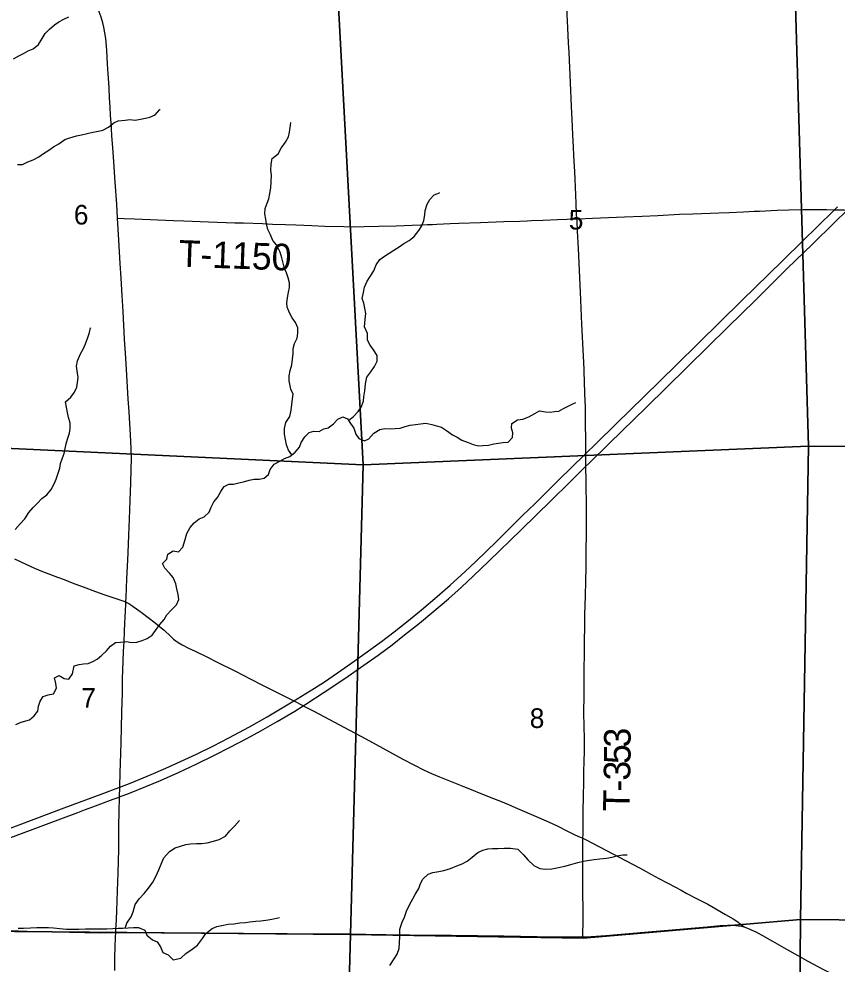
# Model space of a CAD drawing. Extents: x 0 to 34, y 0 to 22.
# Drawn here: x 11.919 to 13.666, y 11.182 to 13.199 of the extents above; entities that cross this region are included whole.
import ezdxf

# ---------------------------------------------------------------- set-up
doc = ezdxf.new("R2010")
doc.units = 0
for name, color, linetype in [('GM_X_County_Road', 7, 'Continuous'), ('GM_X_Interstate_Location', 7, 'Continuous'), ('GM_X_Interstate_Route', 7, 'Continuous'), ('GM_X_Minor_River', 7, 'Continuous'), ('GM_X_Section', 7, 'Continuous'), ('GM_X_Section_Text', 7, 'Continuous'), ('GM_X_State_Location', 7, 'Continuous'), ('GM_X_State_Route', 7, 'Continuous'), ('GM_X_Township_Road', 7, 'Continuous'), ('GM_X_Township_Road_Text', 7, 'Continuous')]:
    doc.layers.add(name, color=color, linetype=linetype)

msp = doc.modelspace()

# ---------------------------------------------------------------- linework, layer by layer
at = {"layer": 'GM_X_County_Road'}
for points in [[(13.1228, 11.2399), (13.1404, 11.2408), (13.1714, 11.2429), (13.2704, 11.2513), (13.3137, 11.2552), (13.354, 11.2584), (13.388, 11.2616), (13.4158, 11.2643), (13.4313, 11.2651), (13.4424, 11.2652), (13.4496, 11.2644), (13.4553, 11.2636), (13.4616, 11.2624), (13.4671, 11.2609)], [(13.4671, 11.2609), (13.4723, 11.2592), (13.478, 11.2569), (13.4823, 11.2551), (13.4923, 11.2503), (13.506, 11.243), (13.5275, 11.2307), (13.5572, 11.2137), (13.5814, 11.1998), (13.6032, 11.1878), (13.6363, 11.1705), (13.6668, 11.1552), (13.6919, 11.1429), (13.762, 11.1094), (13.8094, 11.0862), (13.843, 11.07), (13.8851, 11.05), (13.9075, 11.0392), (13.9465, 11.0201), (13.9745, 11.0065), (14.0109, 10.989), (14.0473, 10.9715), (14.078, 10.9566), (14.0833, 10.954)], [(11.8989, 11.2535), (11.9362, 11.2521), (11.9704, 11.2512), (11.9983, 11.2507), (12.0266, 11.25), (12.0426, 11.2496), (12.059, 11.2493), (12.074, 11.249), (12.0918, 11.2485), (12.1162, 11.2489), (12.1255, 11.2492)], [(12.1255, 11.2492), (12.1348, 11.2494), (12.1472, 11.2494), (12.172, 11.2492), (12.1937, 11.249), (12.2228, 11.2488), (12.259, 11.2486), (12.2846, 11.2484), (12.3146, 11.2482), (12.3395, 11.2478), (12.355, 11.2478), (12.3736, 11.2478), (12.3984, 11.2476), (12.4388, 11.2473), (12.4543, 11.247), (12.476, 11.2468), (12.4915, 11.2467), (12.5101, 11.2465), (12.5536, 11.2464), (12.6064, 11.246), (12.628, 11.246), (12.659, 11.2455), (12.6745, 11.2452), (12.7025, 11.2448), (12.7242, 11.2445), (12.7522, 11.2442), (12.777, 11.2438), (12.8111, 11.2434), (12.8422, 11.2432), (12.8763, 11.243), (12.898, 11.2426), (12.954, 11.2418), (13.0254, 11.2409), (13.0813, 11.2399), (13.1031, 11.2396), (13.1217, 11.2399), (13.1228, 11.2399)]]:
    msp.add_lwpolyline(points, dxfattribs=at)
at = {"layer": 'GM_X_Interstate_Route'}
for points in [[(11.8349, 11.448), (11.9194, 11.4792), (12.0154, 11.5153), (12.0941, 11.5443), (12.132, 11.5584), (12.1339, 11.5592), (12.1581, 11.5686), (12.2012, 11.5864), (12.2326, 11.5999), (12.2638, 11.614), (12.2975, 11.6299), (12.3337, 11.6478), (12.3669, 11.6649), (12.4107, 11.6885), (12.4487, 11.7097), (12.481, 11.7284), (12.5057, 11.7434), (12.5129, 11.7477), (12.5498, 11.7708), (12.5707, 11.7843), (12.5991, 11.8034), (12.6347, 11.8284), (12.6575, 11.8446), (12.6927, 11.8703), (12.7199, 11.891), (12.7468, 11.9122), (12.778, 11.9379), (12.8113, 11.966), (12.8393, 11.9905), (12.8716, 12.0197), (12.8943, 12.041), (12.9389, 12.0844), (12.9807, 12.1261), (12.994, 12.1391), (13.0208, 12.1651), (13.0694, 12.2131), (13.1005, 12.2436), (13.125, 12.2674), (13.1289, 12.2713), (13.1494, 12.2914), (13.1938, 12.3348), (13.2537, 12.3936), (13.3224, 12.4611), (13.4622, 12.5982), (13.5487, 12.6831), (13.5932, 12.7265), (13.6221, 12.7547), (13.6597, 12.7919), (13.6663, 12.7984)], [(12.1304, 11.5375), (12.1333, 11.5386), (12.1547, 11.5469), (12.1893, 11.5607), (12.2208, 11.5739), (12.2605, 11.5915), (12.2971, 11.6086), (12.3362, 11.6276), (12.3694, 11.6444), (12.4052, 11.6631), (12.4351, 11.6795), (12.4701, 11.6996), (12.5075, 11.7218), (12.5257, 11.7332), (12.5312, 11.7366), (12.5702, 11.762), (12.6142, 11.7913), (12.6551, 11.8195), (12.6854, 11.8411), (12.7152, 11.8635), (12.7422, 11.8844), (12.7737, 11.9097), (12.8, 11.9315), (12.8355, 11.9617), (12.8634, 11.9864), (12.8885, 12.0096), (12.9222, 12.0417), (12.9913, 12.1089), (13.0555, 12.1721), (13.0931, 12.2092), (13.1265, 12.2417), (13.1292, 12.2443), (13.1355, 12.2504), (13.1799, 12.2938), (13.2575, 12.37), (13.4329, 12.5419), (13.4906, 12.5984), (13.5591, 12.6662), (13.6127, 12.7181), (13.6592, 12.7639), (13.687, 12.7913)], [(11.8957, 11.4501), (11.9773, 11.4804), (12.0443, 11.5053), (12.0587, 11.5109), (12.0763, 11.5174), (12.0938, 11.5237), (12.12, 11.5335), (12.1304, 11.5375)]]:
    msp.add_lwpolyline(points, dxfattribs=at)
at = {"layer": 'GM_X_Minor_River'}
for points in [[(11.9069, 13.1138), (11.9186, 13.1201), (11.9285, 13.1253), (11.9381, 13.1309), (11.9491, 13.1354), (11.9601, 13.1448), (11.9682, 13.1576), (11.9743, 13.1682), (11.9839, 13.1775), (11.9946, 13.1869), (12.0041, 13.1929), (12.0147, 13.1989), (12.0254, 13.2033)], [(11.9159, 12.8883), (11.9265, 12.8882), (11.9379, 12.8942), (11.9493, 12.8982), (11.9611, 12.9049), (11.9714, 12.912), (11.9828, 12.9191), (11.9927, 12.9259), (12.0038, 12.9326), (12.0163, 12.942), (12.0274, 12.9457), (12.0414, 12.9497), (12.052, 12.9519), (12.0645, 12.9544), (12.0763, 12.9573), (12.0884, 12.9599), (12.0979, 12.9617), (12.1101, 12.9684), (12.1212, 12.9774), (12.1307, 12.9815), (12.1451, 12.9828), (12.1553, 12.9843), (12.167, 12.983), (12.178, 12.9852), (12.1886, 12.9873), (12.1981, 12.9895), (12.2095, 12.9943), (12.2198, 13.0056), (12.2199, 13.006)], [(12.5015, 12.2688), (12.4943, 12.279), (12.4902, 12.29), (12.4877, 12.3014), (12.4859, 12.3132), (12.4856, 12.3246), (12.4883, 12.3378), (12.4972, 12.3503), (12.4999, 12.3639), (12.5015, 12.3764), (12.5024, 12.3882), (12.504, 12.3984), (12.4995, 12.4091), (12.4959, 12.4266), (12.4956, 12.4372), (12.498, 12.4489), (12.5015, 12.461), (12.504, 12.4853), (12.5041, 12.4959), (12.5072, 12.5061), (12.513, 12.5178), (12.5142, 12.5284), (12.5139, 12.5398), (12.5091, 12.5513), (12.5023, 12.5612), (12.496, 12.5719), (12.4916, 12.5837), (12.4909, 12.5932), (12.4921, 12.6038), (12.4945, 12.6159), (12.4965, 12.6261), (12.4962, 12.636), (12.4936, 12.6467), (12.4899, 12.6573), (12.4858, 12.6668), (12.4825, 12.6779), (12.4796, 12.6893), (12.4763, 12.7015), (12.4685, 12.7167), (12.4606, 12.7263), (12.4554, 12.7381), (12.4502, 12.7495), (12.4473, 12.7621), (12.4458, 12.7716), (12.4433, 12.7834), (12.4441, 12.7947), (12.4484, 12.8057), (12.4519, 12.8155), (12.4542, 12.8265), (12.4566, 12.839), (12.4575, 12.8519), (12.458, 12.8659), (12.4566, 12.8766), (12.457, 12.8891), (12.4594, 12.9012), (12.472, 12.911), (12.4782, 12.9234), (12.4877, 12.9359), (12.4943, 12.9472), (12.4962, 12.9574), (12.4994, 12.9771), (12.4975, 12.9767)], [(12.6224, 12.3418), (12.6327, 12.3508), (12.6427, 12.361), (12.6496, 12.3708), (12.6542, 12.3833), (12.655, 12.3927), (12.657, 12.4053), (12.6583, 12.4204), (12.6611, 12.4344), (12.6703, 12.4457), (12.6779, 12.457), (12.6837, 12.4687), (12.6834, 12.4805), (12.6756, 12.4931), (12.6688, 12.5027), (12.6629, 12.5137), (12.663, 12.5278), (12.6563, 12.5422), (12.6576, 12.5578), (12.6592, 12.5703), (12.6574, 12.5817), (12.6548, 12.5927), (12.6515, 12.6026), (12.6543, 12.6151), (12.6563, 12.6265), (12.6621, 12.6393), (12.6686, 12.6495), (12.6763, 12.6612), (12.6817, 12.6744), (12.6893, 12.6854), (12.6992, 12.6928), (12.7091, 12.6992), (12.719, 12.7059), (12.7305, 12.7126), (12.7404, 12.7198), (12.7518, 12.7265), (12.7625, 12.7351), (12.7724, 12.7475), (12.7789, 12.7577), (12.7828, 12.7687), (12.7852, 12.7808), (12.786, 12.7903), (12.7899, 12.8039), (12.7961, 12.8137), (12.8049, 12.8235), (12.8163, 12.8283), (12.8159, 12.8287)], [(12.0059, 12.2401), (12.0075, 12.2499), (12.011, 12.2605), (12.0152, 12.2719), (12.0176, 12.2825), (12.0196, 12.2923), (12.0223, 12.3025), (12.0269, 12.315), (12.0282, 12.3249), (12.0279, 12.337), (12.0242, 12.3484), (12.0224, 12.3591), (12.0202, 12.3705), (12.0184, 12.3819), (12.0291, 12.392), (12.0375, 12.4026), (12.0422, 12.4131), (12.0438, 12.423), (12.045, 12.4336), (12.0436, 12.4431), (12.0418, 12.4583), (12.0434, 12.4697), (12.05, 12.484), (12.0565, 12.4957), (12.0607, 12.5059), (12.0658, 12.5192), (12.0693, 12.5297), (12.0716, 12.5396), (12.0716, 12.5392)], [(12.2533, 11.9933), (12.2477, 12.0066), (12.2402, 12.0162), (12.2301, 12.0265), (12.2249, 12.0365), (12.2344, 12.0462), (12.2368, 12.0565), (12.2482, 12.0639), (12.2596, 12.0619), (12.2687, 12.0717), (12.2734, 12.088), (12.2773, 12.1005), (12.2839, 12.1133), (12.293, 12.1238), (12.3033, 12.1321), (12.3143, 12.1361), (12.3247, 12.1467), (12.3289, 12.1569), (12.3347, 12.1682), (12.3423, 12.178), (12.35, 12.1908), (12.3569, 12.201), (12.3668, 12.2058), (12.3767, 12.2061), (12.388, 12.2087), (12.3979, 12.2108), (12.41, 12.2145), (12.4211, 12.2171), (12.4317, 12.217), (12.4419, 12.2188), (12.4518, 12.2266), (12.4553, 12.2376), (12.4637, 12.2485), (12.4759, 12.2552), (12.4858, 12.2608), (12.4972, 12.2653), (12.5082, 12.2743), (12.5174, 12.2852), (12.5209, 12.2954), (12.529, 12.3071), (12.5385, 12.3165), (12.5484, 12.319), (12.5594, 12.3186), (12.5696, 12.3241), (12.5791, 12.3267), (12.5902, 12.3346), (12.5997, 12.3447), (12.61, 12.3496), (12.6198, 12.3453), (12.6269, 12.3357), (12.634, 12.3254), (12.6381, 12.3132), (12.6441, 12.3037), (12.6561, 12.2983), (12.666, 12.3031), (12.6767, 12.3148), (12.6889, 12.323), (12.6999, 12.3251), (12.7113, 12.3243), (12.7219, 12.3253), (12.7325, 12.3256), (12.7435, 12.3289), (12.7541, 12.3318), (12.7651, 12.3336), (12.7761, 12.3346), (12.7875, 12.3361), (12.7999, 12.3337), (12.8101, 12.3309), (12.8211, 12.3278), (12.8313, 12.3208), (12.8441, 12.3116), (12.8542, 12.3062), (12.8644, 12.3), (12.8776, 12.295), (12.8886, 12.2911), (12.8995, 12.2883), (12.9094, 12.289), (12.9215, 12.2896), (12.9329, 12.2921), (12.9424, 12.2939), (12.9518, 12.295), (12.9632, 12.2956), (12.9724, 12.3054), (12.9732, 12.3156), (12.9703, 12.3255), (12.9711, 12.3358), (12.9829, 12.3436), (12.9947, 12.3447), (13.0076, 12.3495), (13.0202, 12.3569), (13.0301, 12.3625), (13.0429, 12.3605), (13.0527, 12.3596), (13.0622, 12.3611), (13.0717, 12.3621), (13.0816, 12.3673), (13.0915, 12.3729), (13.1014, 12.3778), (13.1075, 12.3804)], [(11.9105, 12.1097), (11.9212, 12.1218), (11.9315, 12.1319), (11.9396, 12.1455), (11.9487, 12.1564), (11.9583, 12.1654), (11.9678, 12.1752), (11.9781, 12.1831), (11.9873, 12.1947), (11.9935, 12.2068), (11.9981, 12.217), (12.0024, 12.2299), (12.0059, 12.2401)], [(11.9122, 11.6931), (11.9233, 11.6983), (11.9411, 11.703), (11.951, 11.7113), (11.9591, 11.7214), (11.9603, 11.7324), (11.9638, 11.7427), (11.9703, 11.7528), (11.9813, 11.7565), (11.9927, 11.7583), (11.9989, 11.7708), (11.9974, 11.781), (11.9949, 11.7924), (12.0048, 11.7977), (12.0153, 11.7911), (12.0255, 11.7902), (12.0332, 11.8012), (12.0364, 11.8186), (12.047, 11.8215), (12.0565, 11.8226), (12.0667, 11.8236), (12.0762, 11.8273), (12.0857, 11.8329), (12.0953, 11.8412), (12.1059, 11.8502), (12.1143, 11.86), (12.125, 11.8682), (12.1352, 11.8692), (12.1478, 11.8703), (12.1595, 11.8682), (12.1705, 11.8689), (12.1815, 11.8726), (12.1921, 11.8767), (12.2028, 11.8838), (12.2104, 11.8935), (12.2192, 11.9064), (12.2284, 11.9173), (12.2346, 11.9271), (12.2437, 11.9372), (12.2548, 11.9485), (12.2598, 11.9602), (12.2584, 11.9705), (12.2559, 11.9827), (12.2533, 11.9933)], [(12.1456, 11.2586), (12.1491, 11.2691), (12.1585, 11.2828), (12.1623, 11.2931), (12.1671, 11.309), (12.1755, 11.3212), (12.1857, 11.3326), (12.1951, 11.3436), (12.2042, 11.3566), (12.2117, 11.3702), (12.2174, 11.3828), (12.2238, 11.3984), (12.2283, 11.4086), (12.24, 11.4223), (12.2525, 11.4296), (12.2639, 11.4334), (12.2753, 11.4368), (12.2847, 11.4384), (12.298, 11.4388), (12.3086, 11.4388), (12.3204, 11.4408), (12.3337, 11.4438), (12.3462, 11.4477), (12.3594, 11.4549), (12.3692, 11.4663), (12.3787, 11.4759), (12.3897, 11.488)], [(12.7104, 11.1786), (12.7198, 11.1927), (12.7262, 11.2026), (12.7304, 11.2147), (12.7315, 11.2273), (12.7322, 11.2409), (12.7318, 11.2565), (12.737, 11.2709), (12.7415, 11.2819), (12.7464, 11.2945), (12.7525, 11.3081), (12.7593, 11.3207), (12.7645, 11.3302), (12.7725, 11.3431), (12.7759, 11.3534), (12.7811, 11.3632), (12.7925, 11.3735), (12.8023, 11.3774), (12.8152, 11.3797), (12.8255, 11.3816), (12.8403, 11.3858), (12.8539, 11.3912), (12.8653, 11.3958), (12.8755, 11.4015), (12.8861, 11.4099), (12.8982, 11.4201), (12.9092, 11.4247), (12.9198, 11.4274), (12.93, 11.4286), (12.9414, 11.4286), (12.9543, 11.429), (12.968, 11.4291), (12.9839, 11.4268), (12.9957, 11.4151), (13.0052, 11.4045), (13.0181, 11.3924), (13.0311, 11.386), (13.0425, 11.3845), (13.0565, 11.3853), (13.0709, 11.3877), (13.0845, 11.3907), (13.0971, 11.3942), (13.1118, 11.3984), (13.1243, 11.4011), (13.1372, 11.4038), (13.1467, 11.405), (13.1589, 11.4061), (13.1733, 11.4077), (13.185, 11.41), (13.1949, 11.4127), (13.2081, 11.415), (13.2176, 11.415)], [(11.9173, 11.2582), (11.9283, 11.2586), (11.9431, 11.2594), (11.9571, 11.2598), (11.9708, 11.2595), (11.9818, 11.2599), (11.9924, 11.2591), (12.0057, 11.2577), (12.0205, 11.2566), (12.0368, 11.2563), (12.0463, 11.2563), (12.0611, 11.2567), (12.0732, 11.2571), (12.1066, 11.2572), (12.1191, 11.2576), (12.1305, 11.2581), (12.1404, 11.2581), (12.1521, 11.2593), (12.1635, 11.2597), (12.1741, 11.2601), (12.1874, 11.2544), (12.1916, 11.2438), (12.2038, 11.2336), (12.214, 11.2295), (12.2209, 11.2185), (12.2262, 11.2067), (12.2373, 11.2018), (12.2479, 11.1905), (12.2642, 11.1947), (12.2752, 11.2046), (12.2888, 11.2138), (12.2998, 11.2221), (12.3107, 11.2362), (12.3179, 11.2472), (12.3312, 11.2579), (12.3414, 11.2617), (12.3516, 11.2644), (12.3657, 11.2667), (12.3774, 11.2679), (12.3903, 11.2695), (12.4021, 11.2706), (12.4119, 11.2718), (12.4244, 11.273), (12.4354, 11.2742), (12.451, 11.2761), (12.462, 11.278)], [(12.462, 11.278), (12.4749, 11.2811)]]:
    msp.add_lwpolyline(points, dxfattribs=at)
at = {"layer": 'GM_X_Section'}
for points in [[(12.4929, 13.3075), (12.5967, 13.3052), (12.6535, 12.2476), (11.5966, 12.2962), (11.6037, 13.3127)], [(13.5034, 13.3022), (13.5746, 13.3006), (13.6043, 12.2869), (12.6535, 12.2476), (12.5967, 13.3052)], [(14.5623, 13.2983), (14.5977, 12.2808), (13.6043, 12.2869), (13.5746, 13.3006), (14.5077, 13.2997)], [(11.5966, 12.2962), (12.6535, 12.2476), (12.6265, 11.2451), (11.591, 11.2544), (11.5914, 11.2691), (11.5959, 12.2894)], [(13.6043, 12.2869), (13.5876, 11.2769), (13.123, 11.237), (12.6265, 11.2451), (12.6535, 12.2476)], [(13.6043, 12.2869), (14.5977, 12.2808), (14.5738, 11.2682), (13.5876, 11.2769)], [(12.6265, 11.2451), (13.123, 11.237), (13.5876, 11.2769), (13.5789, 10.274), (13.086, 10.2295), (12.599, 10.2335)], [(13.5876, 11.2769), (14.5738, 11.2682), (14.5701, 10.2676), (13.5789, 10.274)], [(11.591, 11.2544), (12.6265, 11.2451), (12.599, 10.2335), (11.5847, 10.2523), (11.5843, 10.269)]]:
    msp.add_lwpolyline(points, close=True, dxfattribs=at)
at = {"layer": 'GM_X_State_Route'}
for points in [[(12.108, 13.1024), (12.1061, 13.1327), (12.104, 13.1574), (12.1023, 13.1697), (12.1, 13.1818), (12.0977, 13.1908), (12.0941, 13.2026), (12.0898, 13.2142), (12.0849, 13.2256), (12.0755, 13.2452), (12.0561, 13.2841), (12.0441, 13.3076)], [(12.1232, 11.1679), (12.1237, 11.1959), (12.1242, 11.2176), (12.125, 11.2393), (12.1255, 11.2492), (12.1258, 11.2548), (12.1267, 11.2765), (12.1273, 11.2965), (12.1282, 11.3151), (12.1292, 11.3393), (12.1297, 11.3561), (12.1304, 11.3773), (12.131, 11.399), (12.1317, 11.4283), (12.1321, 11.4593), (12.132, 11.4806), (12.1324, 11.5022), (12.1326, 11.5146), (12.133, 11.5302), (12.1333, 11.5386), (12.1339, 11.5592), (12.134, 11.5612), (12.1349, 11.5892), (12.1355, 11.6114), (12.136, 11.6308), (12.1367, 11.6552), (12.1376, 11.6861), (12.1386, 11.7198), (12.1397, 11.7597), (12.1395, 11.7905), (12.1412, 11.8282), (12.1421, 11.8493), (12.1433, 11.8704), (12.1441, 11.8919), (12.1448, 11.9096), (12.1455, 11.9221), (12.146, 11.9361), (12.1467, 11.9495), (12.1471, 11.9548), (12.1477, 11.9645), (12.1493, 12.0041), (12.151, 12.0443), (12.1516, 12.0598), (12.1533, 12.097), (12.1548, 12.1311), (12.1563, 12.1714), (12.1574, 12.2087), (12.1584, 12.2366), (12.1588, 12.2614), (12.1585, 12.28), (12.1577, 12.2986), (12.1539, 12.3606), (12.1519, 12.3885), (12.1499, 12.4258), (12.1484, 12.4506), (12.1469, 12.4754), (12.1443, 12.5157), (12.141, 12.5746), (12.1389, 12.6087), (12.1371, 12.6459), (12.1351, 12.6769), (12.1322, 12.7266), (12.1293, 12.7741), (12.1275, 12.8041), (12.1241, 12.8506), (12.1211, 12.894), (12.1188, 12.9249), (12.1172, 12.9498), (12.1162, 12.9652), (12.1154, 12.9776), (12.1144, 12.9931), (12.1133, 13.0117), (12.1123, 13.0303), (12.111, 13.052), (12.1087, 13.0924), (12.108, 13.1024)]]:
    msp.add_lwpolyline(points, dxfattribs=at)
at = {"layer": 'GM_X_Township_Road'}
for points in [[(13.1046, 12.8843), (13.1034, 12.9074), (13.1025, 12.926), (13.1012, 12.9508), (13.1003, 12.9694), (13.0984, 13.0128), (13.0962, 13.0625), (13.0931, 13.1276), (13.092, 13.1484), (13.0905, 13.1803), (13.0891, 13.2084), (13.0874, 13.2518), (13.0861, 13.2786), (13.0858, 13.2887), (13.0851, 13.2951), (13.084, 13.2984), (13.0824, 13.3009), (13.0802, 13.3029), (13.0779, 13.3042), (13.0751, 13.3054), (13.0722, 13.306), (13.0696, 13.3064)], [(13.1101, 12.7727), (13.1094, 12.7834), (13.1086, 12.8051), (13.1078, 12.8237), (13.1052, 12.8733), (13.1046, 12.8843)], [(13.4884, 12.7885), (13.5001, 12.7889), (13.5374, 12.7908), (13.5622, 12.7917), (13.5933, 12.7926), (13.6182, 12.7927), (13.6431, 12.7922), (13.6597, 12.7919), (13.6804, 12.7914), (13.687, 12.7913), (13.7053, 12.7911), (13.7923, 12.7901), (13.8202, 12.7897), (13.8513, 12.7892), (13.8642, 12.789)], [(12.1293, 12.7741), (12.1434, 12.7734), (12.1651, 12.7722), (12.2489, 12.7687), (12.2707, 12.768), (12.3235, 12.7663), (12.3793, 12.7643), (12.3983, 12.7636), (12.4384, 12.7622), (12.4601, 12.7614), (12.4881, 12.7606), (12.5099, 12.7596), (12.544, 12.7581), (12.5719, 12.757), (12.6123, 12.7558), (12.6341, 12.7557), (12.6558, 12.7558), (12.6869, 12.7565), (12.7241, 12.7578), (12.7583, 12.7592), (12.777, 12.7599), (12.7899, 12.7603)], [(12.7899, 12.7603), (12.8018, 12.7607), (12.8111, 12.7612), (12.839, 12.7624), (12.8576, 12.7631), (12.9042, 12.7646), (12.954, 12.7665), (12.9881, 12.7678), (13.0037, 12.7685), (13.013, 12.7689), (13.0378, 12.7697), (13.0688, 12.7712), (13.1101, 12.7727)], [(13.1101, 12.7727), (13.1123, 12.7728), (13.1433, 12.7736), (13.1775, 12.7752), (13.2118, 12.7767), (13.249, 12.778), (13.2827, 12.7795), (13.3292, 12.7821), (13.3572, 12.7833), (13.4131, 12.7853), (13.4349, 12.7863), (13.4659, 12.7875), (13.4884, 12.7885)], [(13.1257, 12.4445), (13.1254, 12.4514), (13.1243, 12.4793), (13.1208, 12.5476), (13.1175, 12.6158), (13.1134, 12.709), (13.1115, 12.7462), (13.1104, 12.7679), (13.1101, 12.7727)], [(13.1299, 12.0574), (13.13, 12.0634), (13.1306, 12.1007), (13.1306, 12.1286), (13.1306, 12.1659), (13.1298, 12.2), (13.1294, 12.2155), (13.1292, 12.2404), (13.1292, 12.2443), (13.1289, 12.2683), (13.1289, 12.2713), (13.1287, 12.2963), (13.1284, 12.3397), (13.128, 12.371), (13.1271, 12.3988), (13.1264, 12.4266), (13.1257, 12.4445)], [(11.9092, 12.0464), (11.9318, 12.036), (11.9516, 12.0271), (11.9687, 12.0198), (11.9803, 12.0154), (12.0007, 12.0079), (12.0153, 12.0025), (12.0326, 11.9956), (12.0617, 11.9846), (12.082, 11.9768), (12.0996, 11.9705), (12.1424, 11.9567), (12.1471, 11.9548)], [(13.1229, 11.4504), (13.1231, 11.4591), (13.1236, 11.5088), (13.1242, 11.5398), (13.1245, 11.5709), (13.1246, 11.5802), (13.1248, 11.5926), (13.1253, 11.6143), (13.1259, 11.636), (13.126, 11.6453), (13.1259, 11.6576), (13.1259, 11.6669), (13.1259, 11.6731), (13.1258, 11.6791), (13.1257, 11.6822), (13.1257, 11.6852), (13.1252, 11.6941), (13.1253, 11.7001), (13.1251, 11.7073), (13.1251, 11.7165), (13.1251, 11.7271), (13.1256, 11.7468), (13.1252, 11.7661), (13.1255, 11.7809), (13.1256, 11.7933), (13.1256, 11.8158), (13.1261, 11.8399), (13.1262, 11.8748), (13.1267, 11.8994), (13.1271, 11.9276), (13.1281, 11.9669), (13.1289, 11.9995), (13.1294, 12.0275), (13.1299, 12.0574)], [(12.1471, 11.9548), (12.1492, 11.9539), (12.1535, 11.9513), (12.1573, 11.9489), (12.1748, 11.9363), (12.1823, 11.9309), (12.1948, 11.9218), (12.2096, 11.9104), (12.2191, 11.9025), (12.2284, 11.8942), (12.2419, 11.8814), (12.2488, 11.8752), (12.2537, 11.8714), (12.2588, 11.8679), (12.2668, 11.8633), (12.2807, 11.8564), (12.2947, 11.8498), (12.3198, 11.8377), (12.342, 11.8265), (12.3809, 11.8071), (12.414, 11.79), (12.4388, 11.7772), (12.4971, 11.7478), (12.5057, 11.7434), (12.5248, 11.7337), (12.5257, 11.7332), (12.5496, 11.7208), (12.6018, 11.6932), (12.6594, 11.6625), (12.6812, 11.6505), (12.7385, 11.6192), (12.7632, 11.606), (12.7826, 11.5962), (12.7995, 11.5884), (12.8167, 11.5812), (12.8629, 11.5627), (12.9264, 11.5373), (12.9466, 11.5293), (12.9638, 11.5221), (12.9781, 11.5161), (13.0182, 11.499), (13.0494, 11.4851), (13.069, 11.4758), (13.0885, 11.4661), (13.1024, 11.4591), (13.1137, 11.454), (13.1193, 11.4518), (13.1229, 11.4504)], [(13.1228, 11.2399), (13.1228, 11.2449), (13.1231, 11.2728), (13.123, 11.2976), (13.1226, 11.3349), (13.1224, 11.3659), (13.1223, 11.3939), (13.1225, 11.4187), (13.1225, 11.4343), (13.1229, 11.4504)], [(13.1229, 11.4504), (13.1296, 11.4467), (13.2433, 11.3875)], [(13.2433, 11.3875), (13.2516, 11.3828), (13.2691, 11.3729), (13.2848, 11.3647), (13.3039, 11.3547)], [(13.3039, 11.3547), (13.3056, 11.3538), (13.3323, 11.3396), (13.3448, 11.3324), (13.3642, 11.3227), (13.3893, 11.3095), (13.4272, 11.2878), (13.4434, 11.2783), (13.4512, 11.2732), (13.4543, 11.271), (13.4559, 11.2697), (13.4597, 11.2668), (13.4632, 11.2639), (13.4671, 11.2609)]]:
    msp.add_lwpolyline(points, dxfattribs=at)

# ---------------------------------------------------------------- texts
at = {"layer": 'GM_X_Interstate_Location'}
for s in ['.', '-', ',']:
    msp.add_text(s, height=0.000189, dxfattribs=at).set_placement((13.0142, 12.1318))
msp.add_text('71', height=0.000189, rotation=0, dxfattribs=at).set_placement((12.9755, 12.0926))
at = {"layer": 'GM_X_Section_Text'}
for s, p in [('6', (12.0359, 12.7603)), ('5', (13.0926, 12.7496)), ('7', (12.0518, 11.7288)), ('8', (13.0093, 11.6857))]:
    msp.add_text(s, height=0.0419, rotation=0, dxfattribs=at).set_placement(p)
at = {"layer": 'GM_X_State_Location'}
for s in ['s', 'r']:
    msp.add_text(s, height=0.000189, dxfattribs=at).set_placement((12.1365, 12.6022))
msp.add_text('89', height=0.000189, rotation=0, dxfattribs=at).set_placement((12.0888, 12.5885))
at = {"layer": 'GM_X_Township_Road_Text'}
for s, height, rotation, p in [('T-1150', 0.05682, 357.944, (12.2589, 12.6705)), ('3', 0.0568, 89.917, (13.2247, 11.644)), ('5', 0.0568, 89.4074, (13.2244, 11.6085)), ('3', 0.0568, 88.9705, (13.2237, 11.573)), ('-', 0.0568, 88.8879, (13.2233, 11.5496)), ('T', 0.0568, 88.8685, (13.2224, 11.5071))]:
    msp.add_text(s, height=height, rotation=rotation, dxfattribs=at).set_placement(p)

doc.saveas('drawing.dxf')
